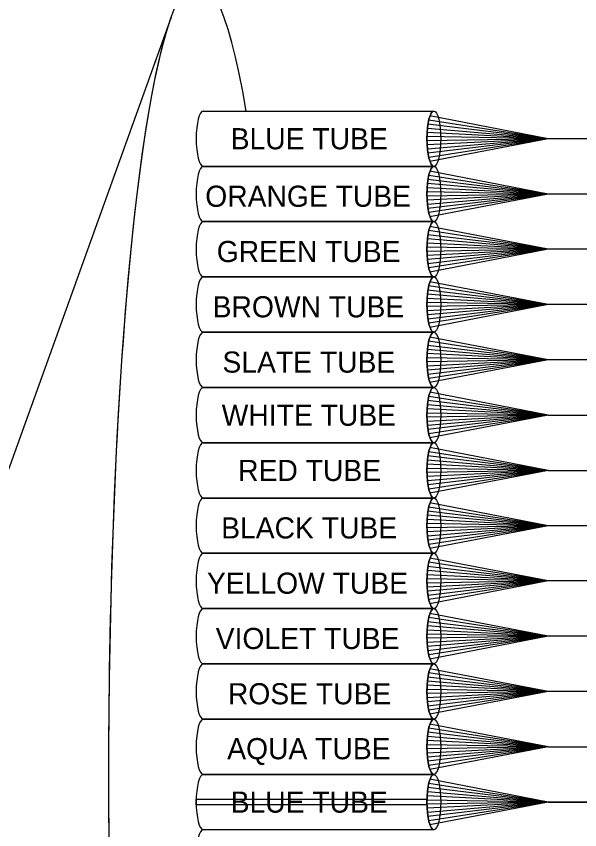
# Model space of a CAD drawing. Extents: x 1805893 to 1833564, y 708898 to 716199.
# Drawn here: x 1831608.1 to 1831669.2, y 714377 to 714465.3 of the extents above; entities that cross this region are included whole.
import ezdxf

# ---------------------------------------------------------------- set-up
doc = ezdxf.new("R2010")
doc.units = 0
doc.layers.add('SH_Data', color=7, linetype='Continuous')

msp = doc.modelspace()

# ---------------------------------------------------------------- linework, layer by layer
at = {"layer": 'SH_Data'}
for p, q in [((1831628.355, 714454.988), (1831653.405, 714454.988)), ((1831628.355, 714454.988), (1831653.405, 714454.988)), ((1831665.826, 714451.988), (1831652.982, 714454.463)), ((1831665.826, 714451.988), (1831652.767, 714453.563)), ((1831665.826, 714451.988), (1831652.852, 714454.013)), ((1831665.826, 714451.988), (1831652.675, 714452.663)), ((1831665.826, 714451.988), (1831652.71, 714453.113)), ((1831665.826, 714451.988), (1831652.658, 714452.213)), ((1831665.826, 714451.988), (1831652.658, 714451.763)), ((1831665.826, 714451.988), (1831652.675, 714451.313)), ((1831665.826, 714451.988), (1831652.71, 714450.863)), ((1831665.826, 714451.988), (1831652.767, 714450.413)), ((1831665.826, 714451.988), (1831652.852, 714449.963)), ((1831665.826, 714451.988), (1831652.982, 714449.513)), ((1831698.027, 714451.988), (1831665.826, 714451.988)), ((1831653.405, 714448.988), (1831628.355, 714448.988)), ((1831628.355, 714448.988), (1831653.405, 714448.988)), ((1831665.826, 714445.988), (1831652.982, 714448.463)), ((1831665.826, 714445.988), (1831652.767, 714447.563)), ((1831665.826, 714445.988), (1831652.852, 714448.013)), ((1831665.826, 714445.988), (1831652.675, 714446.663)), ((1831665.826, 714445.988), (1831652.71, 714447.113)), ((1831665.826, 714445.988), (1831652.658, 714446.213)), ((1831665.826, 714445.988), (1831652.658, 714445.763)), ((1831665.826, 714445.988), (1831652.675, 714445.313)), ((1831665.826, 714445.988), (1831652.71, 714444.863)), ((1831665.826, 714445.988), (1831652.767, 714444.413)), ((1831665.826, 714445.988), (1831652.852, 714443.963)), ((1831665.826, 714445.988), (1831652.982, 714443.513)), ((1831723.135, 714445.988), (1831665.826, 714445.988)), ((1831628.355, 714442.988), (1831653.405, 714442.988)), ((1831653.405, 714442.988), (1831628.355, 714442.988)), ((1831665.826, 714439.988), (1831652.852, 714442.013)), ((1831665.826, 714439.988), (1831652.982, 714442.463)), ((1831665.826, 714439.988), (1831652.71, 714441.113)), ((1831665.826, 714439.988), (1831652.767, 714441.563)), ((1831665.826, 714439.988), (1831652.658, 714440.213)), ((1831665.826, 714439.988), (1831652.675, 714440.663)), ((1831665.826, 714439.988), (1831652.658, 714439.763)), ((1831665.826, 714439.988), (1831652.675, 714439.313)), ((1831665.826, 714439.988), (1831652.71, 714438.863)), ((1831665.826, 714439.988), (1831652.767, 714438.413)), ((1831665.826, 714439.988), (1831652.852, 714437.963)), ((1831665.826, 714439.988), (1831652.982, 714437.513)), ((1831723.135, 714439.988), (1831665.826, 714439.988)), ((1831653.405, 714436.988), (1831628.355, 714436.988)), ((1831628.355, 714436.988), (1831653.405, 714436.988)), ((1831665.826, 714433.988), (1831652.852, 714436.013)), ((1831665.826, 714433.988), (1831652.982, 714436.463)), ((1831665.826, 714433.988), (1831652.71, 714435.113)), ((1831665.826, 714433.988), (1831652.767, 714435.563)), ((1831665.826, 714433.988), (1831652.658, 714434.213)), ((1831665.826, 714433.988), (1831652.658, 714433.763)), ((1831665.826, 714433.988), (1831652.675, 714434.663)), ((1831665.826, 714433.988), (1831652.675, 714433.313)), ((1831665.826, 714433.988), (1831652.71, 714432.863)), ((1831665.826, 714433.988), (1831652.767, 714432.413)), ((1831665.826, 714433.988), (1831652.852, 714431.963)), ((1831665.826, 714433.988), (1831652.982, 714431.513)), ((1831723.135, 714433.988), (1831665.826, 714433.988)), ((1831653.405, 714430.988), (1831628.355, 714430.988)), ((1831628.355, 714430.988), (1831653.405, 714430.988)), ((1831665.826, 714427.988), (1831652.982, 714430.463)), ((1831665.826, 714427.988), (1831652.767, 714429.563)), ((1831665.826, 714427.988), (1831652.852, 714430.013)), ((1831665.826, 714427.988), (1831652.675, 714428.663)), ((1831665.826, 714427.988), (1831652.71, 714429.113)), ((1831665.826, 714427.988), (1831652.658, 714428.213)), ((1831665.826, 714427.988), (1831652.658, 714427.763)), ((1831665.826, 714427.988), (1831652.675, 714427.313)), ((1831665.826, 714427.988), (1831652.71, 714426.863)), ((1831665.826, 714427.988), (1831652.767, 714426.413)), ((1831665.826, 714427.988), (1831652.852, 714425.963)), ((1831665.826, 714427.988), (1831652.982, 714425.513)), ((1831723.135, 714427.988), (1831665.826, 714427.988)), ((1831653.405, 714424.988), (1831628.355, 714424.988)), ((1831628.355, 714424.988), (1831653.405, 714424.988)), ((1831665.826, 714421.988), (1831652.982, 714424.463)), ((1831665.826, 714421.988), (1831652.767, 714423.563)), ((1831665.826, 714421.988), (1831652.852, 714424.013)), ((1831665.826, 714421.988), (1831652.675, 714422.663)), ((1831665.826, 714421.988), (1831652.71, 714423.113)), ((1831665.826, 714421.988), (1831652.658, 714422.213)), ((1831665.826, 714421.988), (1831652.658, 714421.763)), ((1831665.826, 714421.988), (1831652.675, 714421.313)), ((1831665.826, 714421.988), (1831652.71, 714420.863)), ((1831665.826, 714421.988), (1831652.767, 714420.413)), ((1831665.826, 714421.988), (1831652.852, 714419.963)), ((1831665.826, 714421.988), (1831652.982, 714419.513)), ((1831723.135, 714421.962), (1831665.826, 714421.939)), ((1831653.405, 714418.988), (1831628.355, 714418.988)), ((1831628.355, 714418.988), (1831653.405, 714418.988)), ((1831665.826, 714415.988), (1831652.852, 714418.013)), ((1831665.826, 714415.988), (1831652.982, 714418.463)), ((1831665.826, 714415.988), (1831652.767, 714417.563)), ((1831665.826, 714415.988), (1831652.675, 714416.663)), ((1831665.826, 714415.988), (1831652.71, 714417.113)), ((1831665.826, 714415.988), (1831652.658, 714416.213)), ((1831665.826, 714415.988), (1831652.658, 714415.763)), ((1831665.826, 714415.988), (1831652.675, 714415.313)), ((1831665.826, 714415.988), (1831652.71, 714414.863)), ((1831665.826, 714415.988), (1831652.767, 714414.413)), ((1831665.826, 714415.988), (1831652.852, 714413.963)), ((1831665.826, 714415.988), (1831652.982, 714413.513)), ((1831665.826, 714415.988), (1831723.135, 714415.988)), ((1831653.405, 714412.988), (1831628.355, 714412.988)), ((1831628.355, 714412.988), (1831653.405, 714412.988)), ((1831665.826, 714409.988), (1831652.852, 714412.013)), ((1831665.826, 714409.988), (1831652.982, 714412.463)), ((1831665.826, 714409.988), (1831652.71, 714411.113)), ((1831665.826, 714409.988), (1831652.767, 714411.563)), ((1831665.826, 714409.988), (1831652.658, 714410.213)), ((1831665.826, 714409.988), (1831652.675, 714410.663)), ((1831665.826, 714409.988), (1831652.658, 714409.763)), ((1831665.826, 714409.988), (1831652.675, 714409.313)), ((1831665.826, 714409.988), (1831652.71, 714408.863)), ((1831665.826, 714409.988), (1831652.767, 714408.413)), ((1831665.826, 714409.988), (1831652.852, 714407.963)), ((1831665.826, 714409.988), (1831652.982, 714407.513)), ((1831723.135, 714409.988), (1831665.826, 714409.988)), ((1831628.355, 714406.988), (1831653.405, 714406.988)), ((1831653.405, 714406.988), (1831628.355, 714406.988)), ((1831665.826, 714403.988), (1831652.852, 714406.013)), ((1831665.826, 714403.988), (1831652.982, 714406.463)), ((1831665.826, 714403.988), (1831652.71, 714405.113)), ((1831665.826, 714403.988), (1831652.767, 714405.563)), ((1831665.826, 714403.988), (1831652.658, 714404.213)), ((1831665.826, 714403.988), (1831652.658, 714403.763)), ((1831665.826, 714403.988), (1831652.675, 714404.663)), ((1831665.826, 714403.988), (1831652.675, 714403.313)), ((1831665.826, 714403.988), (1831652.71, 714402.863)), ((1831665.826, 714403.988), (1831652.767, 714402.413)), ((1831665.826, 714403.988), (1831652.852, 714401.963)), ((1831665.826, 714403.988), (1831652.982, 714401.513)), ((1831723.135, 714403.988), (1831665.826, 714403.988)), ((1831653.405, 714400.988), (1831628.355, 714400.988)), ((1831628.355, 714400.988), (1831653.405, 714400.988)), ((1831628.355, 714400.988), (1831653.405, 714400.988)), ((1831665.826, 714397.988), (1831652.982, 714400.463)), ((1831665.826, 714397.988), (1831652.767, 714399.563)), ((1831665.826, 714397.988), (1831652.852, 714400.013)), ((1831665.826, 714397.988), (1831652.675, 714398.663)), ((1831665.826, 714397.988), (1831652.71, 714399.113)), ((1831665.826, 714397.988), (1831652.658, 714398.213)), ((1831665.826, 714397.988), (1831652.658, 714397.763)), ((1831665.826, 714397.988), (1831652.675, 714397.313)), ((1831665.826, 714397.988), (1831652.71, 714396.863)), ((1831665.826, 714397.988), (1831652.767, 714396.413)), ((1831665.826, 714397.988), (1831652.852, 714395.963)), ((1831665.826, 714397.988), (1831652.982, 714395.513)), ((1831723.135, 714397.988), (1831665.826, 714397.988)), ((1831653.405, 714394.988), (1831628.355, 714394.988)), ((1831628.355, 714394.988), (1831653.405, 714394.988)), ((1831665.826, 714391.988), (1831652.982, 714394.463)), ((1831665.826, 714391.988), (1831652.767, 714393.563)), ((1831665.826, 714391.988), (1831652.852, 714394.013)), ((1831665.826, 714391.988), (1831652.675, 714392.663)), ((1831665.826, 714391.988), (1831652.71, 714393.113)), ((1831665.826, 714391.988), (1831652.658, 714392.213)), ((1831665.826, 714391.988), (1831652.658, 714391.763)), ((1831665.826, 714391.988), (1831652.675, 714391.313)), ((1831665.826, 714391.988), (1831652.71, 714390.863)), ((1831665.826, 714391.988), (1831652.767, 714390.413)), ((1831665.826, 714391.988), (1831652.852, 714389.963)), ((1831665.826, 714391.988), (1831652.982, 714389.513)), ((1831723.135, 714391.988), (1831665.826, 714391.988)), ((1831653.405, 714388.988), (1831628.355, 714388.988)), ((1831628.355, 714388.988), (1831653.405, 714388.988)), ((1831665.826, 714385.988), (1831652.852, 714388.013)), ((1831665.826, 714385.988), (1831652.982, 714388.463)), ((1831665.826, 714385.988), (1831652.71, 714387.113)), ((1831665.826, 714385.988), (1831652.767, 714387.563)), ((1831665.826, 714385.988), (1831652.675, 714386.663)), ((1831665.826, 714385.988), (1831652.658, 714386.213)), ((1831665.826, 714385.988), (1831652.658, 714385.763)), ((1831665.826, 714385.988), (1831652.675, 714385.313)), ((1831665.826, 714385.988), (1831652.71, 714384.863)), ((1831665.826, 714385.988), (1831652.767, 714384.413)), ((1831665.826, 714385.988), (1831652.852, 714383.963)), ((1831665.826, 714385.988), (1831652.982, 714383.513)), ((1831723.135, 714385.962), (1831665.826, 714385.939)), ((1831653.405, 714382.988), (1831628.355, 714382.988)), ((1831628.355, 714382.988), (1831653.405, 714382.988)), ((1831665.826, 714379.988), (1831652.852, 714382.013)), ((1831665.826, 714379.988), (1831652.982, 714382.463)), ((1831665.826, 714379.988), (1831652.71, 714381.113)), ((1831665.826, 714379.988), (1831652.767, 714381.563)), ((1831665.826, 714379.988), (1831652.658, 714380.213)), ((1831665.826, 714379.988), (1831652.675, 714380.663)), ((1831665.826, 714379.988), (1831652.658, 714379.763)), ((1831665.826, 714379.988), (1831652.675, 714379.313)), ((1831665.826, 714379.988), (1831652.71, 714378.863)), ((1831665.826, 714379.988), (1831652.767, 714378.413)), ((1831665.826, 714379.988), (1831652.852, 714377.963)), ((1831665.826, 714379.988), (1831652.982, 714377.513)), ((1831665.826, 714379.988), (1831723.135, 714379.988)), ((1831723.135, 714379.988), (1831665.826, 714379.988)), ((1831653.405, 714376.988), (1831628.355, 714376.988))]:
    msp.add_line(p, q, dxfattribs=at)
msp.add_lwpolyline([(1831624.879, 714465.184), (1831595.286, 714382.988), (1831624.879, 714300.791)], dxfattribs=at)
msp.add_lwpolyline([(1831624.879, 714465.184), (1831595.286, 714382.988), (1831624.879, 714300.791)], dxfattribs=at)
msp.add_lwpolyline([(1831627.609, 714380.288), (1831652.657, 714380.288), (1831652.657, 714379.688), (1831627.609, 714379.688)], close=True, dxfattribs=at)
for centre, major_axis, ratio, start_param, end_param in [((1831627.752, 714382.988), (0, -86.094), 0.112175, 2.561295, 6.863483), ((1831627.752, 714382.988), (0, -86.094), 0.112175, 2.561295, 6.863483), ((1831627.752, 714382.988), (0, -86.094), 0.112175, 3.443628, 5.98115), ((1831628.355, 714451.988), (0, -3), 0.25, 3.141593, 6.283185), ((1831628.355, 714451.988), (0, -3), 0.25, 3.141593, 6.283185), ((1831653.405, 714451.988), (0, -3), 0.25, 3.141593, 6.283185), ((1831628.355, 714445.988), (0, -3), 0.25, 3.141593, 6.283185), ((1831628.355, 714445.988), (0, -3), 0.25, 3.141593, 6.283185), ((1831653.405, 714445.988), (0, -3), 0.25, 3.141593, 6.283185), ((1831628.355, 714439.988), (0, -3), 0.25, 3.141593, 6.283185), ((1831628.355, 714439.988), (0, -3), 0.25, 3.141593, 6.283185), ((1831653.405, 714439.988), (0, -3), 0.25, 3.141593, 6.283185), ((1831628.355, 714433.988), (0, -3), 0.25, 3.141593, 6.283185), ((1831628.355, 714433.988), (0, -3), 0.25, 3.141593, 6.283185), ((1831653.405, 714433.988), (0, -3), 0.25, 3.141593, 6.283185), ((1831628.355, 714427.988), (0, -3), 0.25, 3.141593, 6.283185), ((1831628.355, 714427.988), (0, -3), 0.25, 3.141593, 6.283185), ((1831653.405, 714427.988), (0, -3), 0.25, 3.141593, 6.283185), ((1831628.355, 714421.988), (0, -3), 0.25, 3.141593, 6.283185), ((1831628.355, 714421.988), (0, -3), 0.25, 3.141593, 6.283185), ((1831653.405, 714421.988), (0, -3), 0.25, 3.141593, 6.283185), ((1831628.355, 714415.988), (0, -3), 0.25, 3.141593, 6.283185), ((1831628.355, 714415.988), (0, -3), 0.25, 3.141593, 6.283185), ((1831653.405, 714415.988), (0, -3), 0.25, 3.141593, 6.283185), ((1831628.355, 714409.988), (0, -3), 0.25, 3.141593, 6.283185), ((1831628.355, 714409.988), (0, -3), 0.25, 3.141593, 6.283185), ((1831653.405, 714409.988), (0, -3), 0.25, 3.141593, 6.283185), ((1831628.355, 714403.988), (0, -3), 0.25, 3.141593, 6.283185), ((1831628.355, 714403.988), (0, -3), 0.25, 3.141593, 6.283185), ((1831653.405, 714403.988), (0, -3), 0.25, 3.141593, 6.283185), ((1831628.355, 714397.988), (0, -3), 0.25, 3.141593, 6.283185), ((1831628.355, 714397.988), (0, -3), 0.25, 3.141593, 6.283185), ((1831653.405, 714397.988), (0, -3), 0.25, 3.141593, 6.283185), ((1831628.355, 714391.988), (0, -3), 0.25, 3.141593, 6.283185), ((1831628.355, 714391.988), (0, -3), 0.25, 3.141593, 6.283185), ((1831653.405, 714391.988), (0, -3), 0.25, 3.141593, 6.283185), ((1831628.355, 714385.988), (0, -3), 0.25, 3.141593, 6.283185), ((1831628.355, 714385.988), (0, -3), 0.25, 3.141593, 6.283185), ((1831653.405, 714385.988), (0, -3), 0.25, 3.141593, 6.283185), ((1831628.355, 714379.988), (0, -3), 0.25, 3.141593, 6.283185), ((1831628.355, 714379.988), (0, -3), 0.25, 3.141593, 6.283185), ((1831653.405, 714379.988), (0, -3), 0.25, 3.141593, 6.283185), ((1831628.355, 714373.988), (0, -3), 0.25, 3.141593, 6.283185)]:
    msp.add_ellipse(centre, major_axis=major_axis, ratio=ratio, start_param=start_param, end_param=end_param, dxfattribs=at)
for centre in [(1831653.405, 714451.988), (1831653.405, 714445.988), (1831653.405, 714439.988), (1831653.405, 714433.988), (1831653.405, 714427.988), (1831653.405, 714421.988), (1831653.405, 714415.988), (1831653.405, 714409.988), (1831653.405, 714403.988), (1831653.405, 714397.988), (1831653.405, 714391.988), (1831653.405, 714385.988), (1831653.405, 714379.988)]:
    msp.add_ellipse(centre, major_axis=(0, -3), ratio=0.25, dxfattribs=at)

# ---------------------------------------------------------------- texts
for s, height, p in [('BLUE TUBE', 2.2947, (1831631.35, 714450.84)), ('ORANGE TUBE', 2.29468, (1831628.59, 714444.599)), ('GREEN TUBE', 2.2947, (1831629.837, 714438.599)), ('BROWN TUBE', 2.2947, (1831629.393, 714432.599)), ('SLATE TUBE', 2.2947, (1831630.459, 714426.599)), ('WHITE TUBE', 2.2947, (1831630.374, 714420.84)), ('RED TUBE', 2.2947, (1831632.162, 714414.84)), ('BLACK TUBE', 2.2947, (1831630.32, 714408.599)), ('YELLOW TUBE', 2.29468, (1831628.776, 714402.599)), ('VIOLET TUBE', 2.29468, (1831629.726, 714396.599)), ('ROSE TUBE', 2.2947, (1831631.049, 714390.599)), ('AQUA TUBE', 2.2947, (1831630.973, 714384.639)), ('BLUE TUBE', 2.2947, (1831631.35, 714378.84))]:
    msp.add_text(s, height=height, dxfattribs=at).set_placement(p)

doc.saveas('drawing.dxf')
